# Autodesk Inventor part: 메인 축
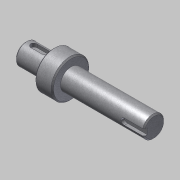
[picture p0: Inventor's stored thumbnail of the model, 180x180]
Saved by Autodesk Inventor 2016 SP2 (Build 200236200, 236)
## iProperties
Created: 2016-04
Part Number: 메인 축
Document SubType Name: Modeling
Designer: mdu
Density: 7.86 g/cm^3
Mass: 230.24 g
Surface Area: 74.3518 cm^2
Volume: 29.2926 cm^3
Material: 강철, 연강
Appearance: 금속-강(스테인리스, 브러시됨)
Author: mdu
Revision Number: 1
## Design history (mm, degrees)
sketch "스케치1"
  geometry: L1 (10.497, -57.5)-(112.497, -57.5); L2 (10.497, -66)-(32.497, -66); L3 (32.497, -72.5)-(46.5, -72.5); L4 (46.5, -66)-(112.497, -66); L5 (112.497, -66)-(112.497, -57.5); L6 (10.497, -66)-(10.497, -57.5); L7 (46.5, -69.749)-(46.5, -45.251) reference; L8 (46.5, -72.5)-(46.5, -66); L9 (32.497, -72.5)-(32.497, -66); L10 (32.497, -35)-(32.497, -80) reference; 3 further points
  constraints: 16 end point, 3 point on line, 2 parallel, 2 perpendicular, 1 collinear, 1 horizontal, 1 midpoint
  dimensions: "d0" = 17 diameter of L4 L1; "d1" = 30 diameter of L3 L1; "d2" = 22 distance of L2.start L2.end; "d3" = 65.99692 distance of L4.start L4.end (derived); "d5" = 17 diameter of L2 L1; "d19" = 80 distance between parallel lines of L5 L9
revolve "회전1" sketch "스케치1" stored, may be unused: angle "d4" = 90 deg
chamfer "모따기1" distance "d6" = 1; stored, may be unused: second distance "d7" = 2, angle "d8" = 45 deg
node "작업 평면1"
sketch "스케치2"
  geometry: L1 (-11, -7.5)-(-11, 7.5) reference; L2 (-4.5, 2.5)-(4.5, 2.5); L3 (4.5, -2.5)-(-4.5, -2.5); A1 r 2.5 centre (4.5, 0) between (4.5, -2.5) and (4.5, 2.5); A2 r 2.5 centre (-4.5, 0) between (-4.5, 2.5) and (-4.5, -2.5); 2 further points
  constraints: 4 end point, 4 point on circle, 4 tangent, 2 centre point, 1 horizontal alignment, 1 midpoint, 1 parallel, 1 perpendicular
  dimensions: "d9" = 5 distance between parallel lines of L3 L2; "d10" = 14 dimension on A1 A2; "d11" = 4 distance edge to line of A2 L1
extrude "돌출1" cut sketch "스케치2" distance "d12" = 3; taper "d13" = 0 deg
node "작업 평면2"
sketch "스케치3"
  geometry: L1 (32.998, 7.5)-(32.998, -7.5) reference; L2 (32.998, 2.5)-(17.498, 2.5); L3 (17.498, -2.5)-(32.998, -2.5); A1 r 2.5 centre (17.498, 0) between (17.498, 2.5) and (17.498, -2.5); 2 further points
  constraints: 4 end point, 2 perpendicular, 2 point on circle, 2 point on line, 2 tangent, 1 centre point, 1 horizontal alignment, 1 midpoint
  dimensions: "d14" = 5 distance between parallel lines of L3 L2; "d15" = 18 dimension on A1 L1
extrude "돌출2" cut sketch "스케치3" distance "d16" = 3; taper "d17" = 0 deg
node "솔리드1"
node "참조4"
node "참조5"
